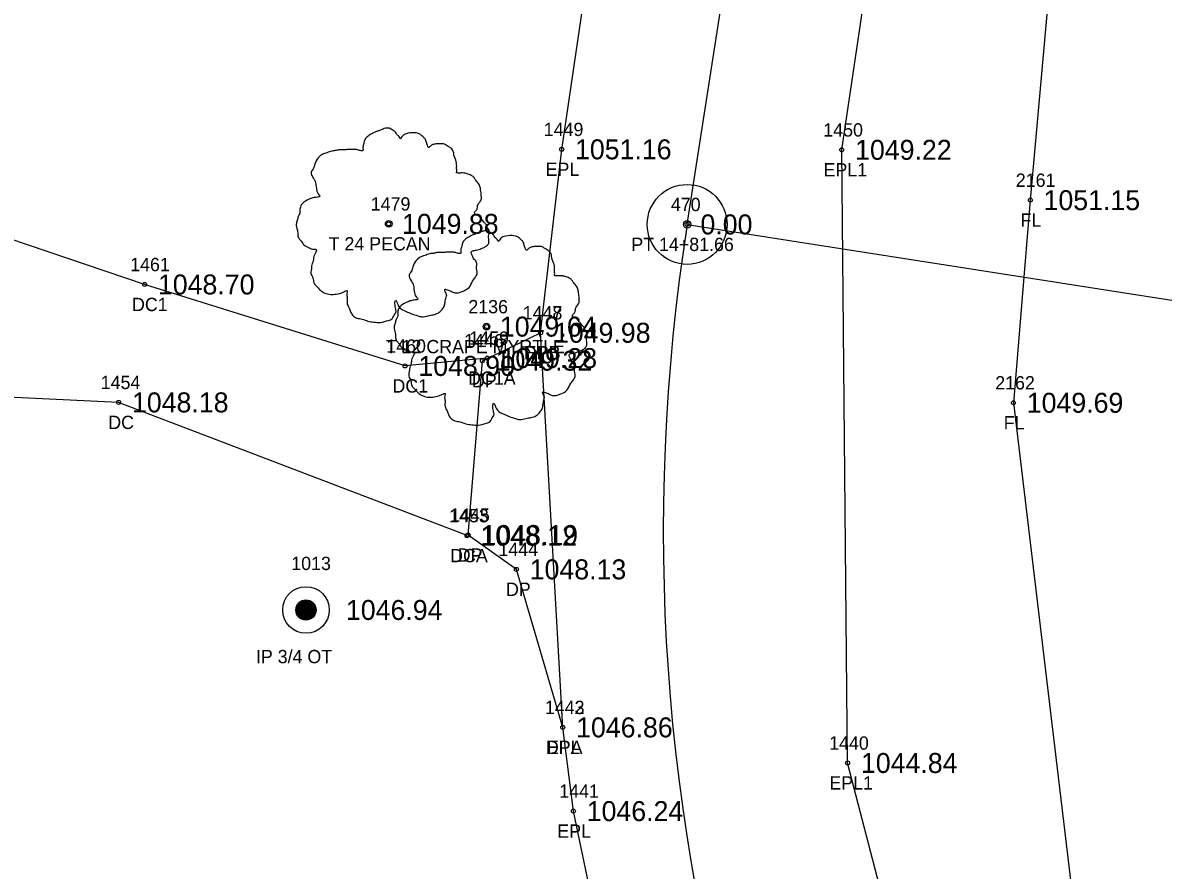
# Model space of a CAD drawing. Extents: x 1578957 to 1581675, y 1115963 to 1120391.
# Drawn here: x 1579731.3 to 1579816.9, y 1117837.9 to 1117901.5 of the extents above; entities that cross this region are included whole.
import ezdxf

# ---------------------------------------------------------------- set-up
doc = ezdxf.new("R2010")
doc.units = 0
for name, color, linetype in [('RD_EX_Conc', 7, 'Continuous'), ('RD_EX_Conc_txCode', 7, 'Continuous'), ('RD_EX_Driveway', 7, 'Continuous'), ('RD_EX_Driveway_txCode', 7, 'Continuous'), ('RD_EX_DV_Prop_txCode', 7, 'Continuous'), ('RD_EX_DV_PropPin', 7, 'Continuous'), ('RD_EX_Fence_Other', 7, 'Continuous'), ('RD_EX_Fence_Other_txCode', 7, 'Continuous'), ('RD_EX_Road', 7, 'Continuous'), ('RD_EX_Road_txCode', 7, 'Continuous'), ('RD_EX_TX_Conc_ELEV', 7, 'Continuous'), ('RD_EX_TX_Driveway_ELEV', 7, 'Continuous'), ('RD_EX_TX_DV_Prop_ELEV', 7, 'Continuous'), ('RD_EX_TX_Fence_Other_ELEV', 7, 'Continuous'), ('RD_EX_TX_Road_ELEV', 7, 'Continuous'), ('RD_EX_TX_VEG_ELEV', 7, 'Continuous'), ('RD_EX_VEG', 7, 'Continuous'), ('RD_EX_VEG_txCode', 7, 'Continuous'), ('RD_HC_Cl', 7, 'Continuous'), ('RD_HC_Data', 7, 'Continuous'), ('RD_HC_Survey_ELEV', 7, 'Continuous'), ('RD_HC_txCode', 7, 'Continuous'), ('RD_SMD_Locator', 7, 'Continuous')]:
    doc.layers.add(name, color=color, linetype=linetype)

msp = doc.modelspace()

# ---------------------------------------------------------------- linework, layer by layer
at = {"layer": 'RD_EX_Conc'}
for points in [[(1579766.13, 1117876.333), (1579759.962, 1117875.743), (1579740.404, 1117881.865), (1579703.901, 1117894.243), (1579686.039, 1117903.999), (1579677.342, 1117923.266), (1579681.088, 1117939.977), (1579691.372, 1117948.591), (1579705.923, 1117954.825), (1579741.024, 1117962.879), (1579773.406, 1117968.489), (1579777.959, 1117966.761), (1579779.093, 1117978.96)], [(1579764.617, 1117862.993), (1579738.454, 1117873.005), (1579671.399, 1117876.222)]]:
    msp.add_lwpolyline(points, dxfattribs=at)
at = {"layer": 'RD_EX_Driveway'}
msp.add_lwpolyline([(1579771.808, 1117848.588), (1579768.323, 1117860.461), (1579764.698, 1117863.037), (1579765.767, 1117876.14), (1579770.145, 1117878.236)], dxfattribs=at)
at = {"layer": 'RD_EX_DV_PropPin'}
for p, q in [((1579752.136, 1117856.752), (1579752.136, 1117858.065)), ((1579752.171, 1117856.733), (1579752.171, 1117858.084)), ((1579752.206, 1117856.716), (1579752.206, 1117858.102)), ((1579752.241, 1117856.701), (1579752.241, 1117858.116)), ((1579752.276, 1117856.688), (1579752.276, 1117858.129)), ((1579752.311, 1117856.677), (1579752.311, 1117858.14)), ((1579752.346, 1117856.668), (1579752.346, 1117858.149)), ((1579752.381, 1117856.661), (1579752.381, 1117858.157)), ((1579752.416, 1117856.655), (1579752.416, 1117858.163)), ((1579752.451, 1117856.651), (1579752.451, 1117858.167)), ((1579752.486, 1117856.649), (1579752.486, 1117858.169)), ((1579752.521, 1117856.648), (1579752.521, 1117858.17)), ((1579752.556, 1117856.649), (1579752.556, 1117858.169)), ((1579752.591, 1117856.651), (1579752.591, 1117858.167)), ((1579752.626, 1117856.655), (1579752.626, 1117858.163)), ((1579752.661, 1117856.661), (1579752.661, 1117858.157)), ((1579752.696, 1117856.668), (1579752.696, 1117858.149)), ((1579752.731, 1117856.677), (1579752.731, 1117858.14)), ((1579752.766, 1117856.688), (1579752.766, 1117858.129)), ((1579752.801, 1117856.701), (1579752.801, 1117858.116)), ((1579752.836, 1117856.716), (1579752.836, 1117858.102)), ((1579752.871, 1117856.733), (1579752.871, 1117858.084)), ((1579752.906, 1117856.752), (1579752.906, 1117858.065)), ((1579751.785, 1117857.213), (1579751.785, 1117857.605)), ((1579751.82, 1117857.111), (1579751.82, 1117857.707)), ((1579751.856, 1117857.039), (1579751.856, 1117857.778)), ((1579751.891, 1117856.982), (1579751.891, 1117857.835)), ((1579751.926, 1117856.935), (1579751.926, 1117857.883)), ((1579751.961, 1117856.894), (1579751.961, 1117857.924)), ((1579751.996, 1117856.858), (1579751.996, 1117857.96)), ((1579752.031, 1117856.827), (1579752.031, 1117857.991)), ((1579752.066, 1117856.799), (1579752.066, 1117858.019)), ((1579752.101, 1117856.774), (1579752.101, 1117858.043)), ((1579752.941, 1117856.774), (1579752.941, 1117858.043)), ((1579752.976, 1117856.799), (1579752.976, 1117858.019)), ((1579753.011, 1117856.827), (1579753.011, 1117857.991)), ((1579753.046, 1117856.858), (1579753.046, 1117857.96)), ((1579753.081, 1117856.894), (1579753.081, 1117857.924)), ((1579753.116, 1117856.935), (1579753.116, 1117857.883)), ((1579753.151, 1117856.982), (1579753.151, 1117857.835)), ((1579753.186, 1117857.039), (1579753.186, 1117857.778)), ((1579753.221, 1117857.111), (1579753.221, 1117857.707)), ((1579753.256, 1117857.213), (1579753.256, 1117857.605))]:
    msp.add_line(p, q, dxfattribs=at)
for radius in [1.75, 0.761]:
    msp.add_circle((1579752.521, 1117857.409), radius, dxfattribs=at)
at = {"layer": 'RD_EX_Fence_Other'}
msp.add_lwpolyline([(1579823.104, 1118041.087), (1579819.64, 1117977.762), (1579811.21, 1117936.274), (1579806.912, 1117888.201), (1579805.65, 1117872.977), (1579810.216, 1117834.804), (1579821.355, 1117805.105), (1579835.234, 1117784.194), (1579851.403, 1117768.05), (1579868.554, 1117757.557), (1579908.33, 1117744.227), (1579949.735, 1117742.637), (1579998.853, 1117745.107), (1580033.637, 1117749.157), (1580057.075, 1117744.228), (1580092.078, 1117730.794), (1580117.524, 1117724.619), (1580141.715, 1117727.925), (1580159.983, 1117735.31), (1580192.445, 1117760.446), (1580226.972, 1117787.769), (1580271.309, 1117822.486), (1580302.096, 1117858.032)], dxfattribs=at)
at = {"layer": 'RD_EX_Road'}
for points in [[(1580132.914, 1117689.949), (1580126.197, 1117690.713), (1580104.514, 1117701.773), (1580054.231, 1117722.915), (1579999.655, 1117728.645), (1579947.034, 1117725.641), (1579902.617, 1117727.901), (1579859.282, 1117741.23), (1579828.335, 1117764.868), (1579804.422, 1117802.726), (1579793.197, 1117845.912), (1579792.758, 1117891.982), (1579799.628, 1117938.215), (1579807.414, 1117987.508), (1579809.684, 1118039.768), (1579804.464, 1118093.359), (1579794.793, 1118143.944)], [(1580121.995, 1117647.598), (1580119.902, 1117658.172), (1580108.554, 1117670.894), (1580093.888, 1117680.496), (1580047.657, 1117700.115), (1579998.943, 1117706.513), (1579949.017, 1117704.446), (1579899.181, 1117706.754), (1579851.312, 1117721.596), (1579810.789, 1117752.923), (1579804.028, 1117759.706), (1579792.304, 1117778.187), (1579787.439, 1117787.947), (1579779.119, 1117811.184), (1579772.603, 1117842.297), (1579771.808, 1117848.588), (1579770.145, 1117878.236), (1579771.725, 1117892.019), (1579778.922, 1117940.842), (1579785.853, 1117982.888), (1579786.73, 1117990.339), (1579789.156, 1118040.245), (1579783.452, 1118089.738), (1579774.288, 1118139.394)]]:
    msp.add_lwpolyline(points, dxfattribs=at)
at = {"layer": 'RD_EX_VEG'}
for centre, radius in [((1579758.734, 1117886.419), 0.25), ((1579758.722, 1117886.401), 0.0001), ((1579766.085, 1117878.698), 0.25), ((1579766.073, 1117878.679), 0.0001)]:
    msp.add_circle(centre, radius, dxfattribs=at)
for points in [[(1579758.866, 1117893.587), (1579758.566, 1117893.612), (1579758.241, 1117893.512), (1579757.992, 1117893.412), (1579757.767, 1117893.337), (1579757.542, 1117893.237), (1579757.242, 1117893.062), (1579757.017, 1117892.862), (1579756.892, 1117892.612), (1579756.842, 1117892.387), (1579756.792, 1117892.112), (1579756.792, 1117891.937), (1579756.667, 1117891.912), (1579756.517, 1117891.937), (1579756.267, 1117892.012), (1579756.017, 1117892.012), (1579755.767, 1117892.012), (1579755.418, 1117891.987), (1579755.068, 1117891.987), (1579754.793, 1117891.937), (1579754.468, 1117891.887), (1579754.093, 1117891.762), (1579753.743, 1117891.637), (1579753.444, 1117891.388), (1579753.194, 1117890.913), (1579753.069, 1117890.563), (1579752.919, 1117890.313), (1579753.069, 1117889.863), (1579753.244, 1117889.513), (1579753.269, 1117889.313), (1579753.344, 1117888.889), (1579753.444, 1117888.664), (1579753.568, 1117888.464), (1579753.494, 1117888.439), (1579753.119, 1117888.389), (1579752.819, 1117888.289), (1579752.394, 1117888.064), (1579752.169, 1117887.839), (1579752.069, 1117887.514), (1579752.044, 1117887.164), (1579751.944, 1117886.965), (1579751.869, 1117886.69), (1579751.844, 1117886.615), (1579751.794, 1117886.29), (1579751.894, 1117885.84), (1579751.919, 1117885.49), (1579752.044, 1117885.265), (1579752.194, 1117885.09), (1579752.369, 1117884.84), (1579752.769, 1117884.616), (1579753.094, 1117884.516), (1579753.294, 1117884.491), (1579753.119, 1117883.991), (1579753.069, 1117883.641), (1579752.944, 1117883.241), (1579752.944, 1117883.166), (1579752.894, 1117882.691), (1579753.044, 1117882.366), (1579753.119, 1117881.992), (1579753.294, 1117881.767), (1579753.568, 1117881.467), (1579753.893, 1117881.242), (1579754.393, 1117881.117), (1579754.793, 1117881.142), (1579755.368, 1117881.317), (1579755.618, 1117881.392), (1579755.593, 1117881.217), (1579755.618, 1117880.842), (1579755.618, 1117880.417), (1579755.767, 1117880.093), (1579755.867, 1117879.818), (1579756.017, 1117879.568), (1579756.342, 1117879.343), (1579756.742, 1117879.268), (1579757.167, 1117879.118), (1579757.617, 1117879.043), (1579758.116, 1117879.018), (1579758.716, 1117879.168), (1579758.991, 1117879.293), (1579759.091, 1117879.468), (1579759.291, 1117879.843), (1579759.241, 1117880.068), (1579759.266, 1117880.667), (1579759.366, 1117880.492), (1579759.541, 1117880.142), (1579760.041, 1117879.843), (1579760.44, 1117879.668), (1579760.915, 1117879.518), (1579761.215, 1117879.443), (1579761.69, 1117879.518), (1579762.065, 1117879.593), (1579762.44, 1117879.718), (1579762.739, 1117879.993), (1579762.914, 1117880.267), (1579762.964, 1117880.542), (1579763.039, 1117880.917), (1579763.089, 1117881.092)], [(1579763.089, 1117881.092), (1579763.014, 1117881.267), (1579762.964, 1117881.517), (1579763.039, 1117881.492), (1579763.214, 1117881.442), (1579763.489, 1117881.317), (1579763.714, 1117881.242), (1579764.039, 1117881.267), (1579764.314, 1117881.367), (1579764.764, 1117881.642), (1579765.038, 1117882.117), (1579765.313, 1117882.516), (1579765.388, 1117882.841), (1579765.338, 1117883.066), (1579765.313, 1117883.566), (1579765.113, 1117883.816), (1579765.063, 1117883.941), (1579764.963, 1117884.341), (1579765.038, 1117884.391), (1579765.313, 1117884.441), (1579765.688, 1117884.566), (1579765.963, 1117884.69), (1579766.188, 1117884.865), (1579766.263, 1117885.09), (1579766.238, 1117885.49), (1579766.288, 1117885.89), (1579766.213, 1117886.04), (1579766.113, 1117886.19), (1579766.038, 1117886.39), (1579765.888, 1117886.54), (1579765.788, 1117886.69), (1579765.688, 1117886.79), (1579765.563, 1117886.94), (1579765.388, 1117887.064), (1579765.238, 1117887.114), (1579765.188, 1117887.264), (1579765.338, 1117887.464), (1579765.388, 1117887.564), (1579765.413, 1117887.789), (1579765.638, 1117888.139), (1579765.688, 1117888.539), (1579765.638, 1117888.964), (1579765.588, 1117889.239), (1579765.438, 1117889.513), (1579765.238, 1117889.763), (1579765.113, 1117889.938), (1579764.938, 1117890.063), (1579764.614, 1117890.188), (1579764.364, 1117890.238), (1579764.014, 1117890.238), (1579763.814, 1117890.288), (1579763.839, 1117890.338), (1579763.839, 1117890.488), (1579763.839, 1117890.763), (1579763.764, 1117891.213), (1579763.614, 1117891.712), (1579763.614, 1117891.737), (1579763.514, 1117891.987), (1579763.289, 1117892.187), (1579763.114, 1117892.287), (1579762.914, 1117892.412), (1579762.664, 1117892.437), (1579762.365, 1117892.437), (1579762.09, 1117892.387), (1579761.89, 1117892.287), (1579761.715, 1117892.162), (1579761.64, 1117892.312), (1579761.54, 1117892.612), (1579761.49, 1117892.762), (1579761.34, 1117892.937), (1579761.115, 1117893.137), (1579760.665, 1117893.262), (1579760.041, 1117893.187), (1579759.741, 1117892.987), (1579759.591, 1117892.812), (1579759.541, 1117892.937), (1579759.341, 1117893.137), (1579759.241, 1117893.312), (1579759.066, 1117893.437), (1579758.916, 1117893.537), (1579758.816, 1117893.587)], [(1579766.217, 1117885.865), (1579765.917, 1117885.89), (1579765.592, 1117885.79), (1579765.342, 1117885.69), (1579765.118, 1117885.615), (1579764.893, 1117885.515), (1579764.593, 1117885.34), (1579764.368, 1117885.14), (1579764.243, 1117884.89), (1579764.193, 1117884.666), (1579764.143, 1117884.391), (1579764.143, 1117884.216), (1579764.018, 1117884.191), (1579763.868, 1117884.216), (1579763.618, 1117884.291), (1579763.368, 1117884.291), (1579763.118, 1117884.291), (1579762.769, 1117884.266), (1579762.419, 1117884.266), (1579762.144, 1117884.216), (1579761.819, 1117884.166), (1579761.444, 1117884.041), (1579761.094, 1117883.916), (1579760.794, 1117883.666), (1579760.545, 1117883.191), (1579760.42, 1117882.841), (1579760.27, 1117882.591), (1579760.42, 1117882.142), (1579760.595, 1117881.792), (1579760.619, 1117881.592), (1579760.694, 1117881.167), (1579760.794, 1117880.942), (1579760.919, 1117880.742), (1579760.844, 1117880.717), (1579760.47, 1117880.667), (1579760.17, 1117880.567), (1579759.745, 1117880.342), (1579759.52, 1117880.118), (1579759.42, 1117879.793), (1579759.395, 1117879.443), (1579759.295, 1117879.243), (1579759.22, 1117878.968), (1579759.195, 1117878.893), (1579759.145, 1117878.568), (1579759.245, 1117878.118), (1579759.27, 1117877.769), (1579759.395, 1117877.544), (1579759.545, 1117877.369), (1579759.72, 1117877.119), (1579760.12, 1117876.894), (1579760.445, 1117876.794), (1579760.644, 1117876.769), (1579760.47, 1117876.269), (1579760.42, 1117875.919), (1579760.295, 1117875.52), (1579760.295, 1117875.445), (1579760.245, 1117874.97), (1579760.395, 1117874.645), (1579760.47, 1117874.27), (1579760.644, 1117874.045), (1579760.919, 1117873.745), (1579761.244, 1117873.52), (1579761.744, 1117873.395), (1579762.144, 1117873.42), (1579762.719, 1117873.595), (1579762.968, 1117873.67), (1579762.943, 1117873.495), (1579762.968, 1117873.121), (1579762.968, 1117872.696), (1579763.118, 1117872.371), (1579763.218, 1117872.096), (1579763.368, 1117871.846), (1579763.693, 1117871.621), (1579764.093, 1117871.546), (1579764.518, 1117871.396), (1579764.968, 1117871.321), (1579765.467, 1117871.296), (1579766.067, 1117871.446), (1579766.342, 1117871.571), (1579766.442, 1117871.746), (1579766.642, 1117872.121), (1579766.592, 1117872.346), (1579766.617, 1117872.946), (1579766.717, 1117872.771), (1579766.892, 1117872.421), (1579767.392, 1117872.121), (1579767.791, 1117871.946), (1579768.266, 1117871.796), (1579768.566, 1117871.721), (1579769.041, 1117871.796), (1579769.416, 1117871.871), (1579769.79, 1117871.996), (1579770.09, 1117872.271), (1579770.265, 1117872.546), (1579770.315, 1117872.821), (1579770.39, 1117873.196), (1579770.44, 1117873.37)], [(1579770.44, 1117873.37), (1579770.365, 1117873.545), (1579770.315, 1117873.795), (1579770.39, 1117873.77), (1579770.565, 1117873.72), (1579770.84, 1117873.595), (1579771.065, 1117873.52), (1579771.39, 1117873.545), (1579771.665, 1117873.645), (1579772.114, 1117873.92), (1579772.389, 1117874.395), (1579772.664, 1117874.795), (1579772.739, 1117875.12), (1579772.689, 1117875.345), (1579772.664, 1117875.844), (1579772.464, 1117876.094), (1579772.414, 1117876.219), (1579772.314, 1117876.619), (1579772.389, 1117876.669), (1579772.664, 1117876.719), (1579773.039, 1117876.844), (1579773.314, 1117876.969), (1579773.539, 1117877.144), (1579773.614, 1117877.369), (1579773.589, 1117877.769), (1579773.639, 1117878.168), (1579773.564, 1117878.318), (1579773.464, 1117878.468), (1579773.389, 1117878.668), (1579773.239, 1117878.818), (1579773.139, 1117878.968), (1579773.039, 1117879.068), (1579772.914, 1117879.218), (1579772.739, 1117879.343), (1579772.589, 1117879.393), (1579772.539, 1117879.543), (1579772.689, 1117879.743), (1579772.739, 1117879.843), (1579772.764, 1117880.068), (1579772.989, 1117880.417), (1579773.039, 1117880.817), (1579772.989, 1117881.242), (1579772.939, 1117881.517), (1579772.789, 1117881.792), (1579772.589, 1117882.042), (1579772.464, 1117882.217), (1579772.289, 1117882.342), (1579771.965, 1117882.467), (1579771.715, 1117882.516), (1579771.365, 1117882.516), (1579771.165, 1117882.566), (1579771.19, 1117882.616), (1579771.19, 1117882.766), (1579771.19, 1117883.041), (1579771.115, 1117883.491), (1579770.965, 1117883.991), (1579770.965, 1117884.016), (1579770.865, 1117884.266), (1579770.64, 1117884.466), (1579770.465, 1117884.566), (1579770.265, 1117884.691), (1579770.015, 1117884.716), (1579769.716, 1117884.716), (1579769.441, 1117884.666), (1579769.241, 1117884.566), (1579769.066, 1117884.441), (1579768.991, 1117884.591), (1579768.891, 1117884.89), (1579768.841, 1117885.04), (1579768.691, 1117885.215), (1579768.466, 1117885.415), (1579768.016, 1117885.54), (1579767.392, 1117885.465), (1579767.092, 1117885.265), (1579766.942, 1117885.09), (1579766.892, 1117885.215), (1579766.692, 1117885.415), (1579766.592, 1117885.59), (1579766.417, 1117885.715), (1579766.267, 1117885.815), (1579766.167, 1117885.865)]]:
    msp.add_spline(points, degree=3, dxfattribs=at)
at = {"layer": 'RD_HC_Cl'}
msp.add_line((1579781.145, 1117886.379), (1579795.16, 1117976.12), dxfattribs=at)
msp.add_arc((1579928.874, 1117863.307), 149.519, 171.12359, 273.23235, dxfattribs=at)
at = {"layer": 'RD_HC_Data'}
msp.add_line((1579781.145, 1117886.379), (1579895.714, 1117868.486), dxfattribs=at)
for radius in [3, 0.282]:
    msp.add_circle((1579781.145, 1117886.379), radius, dxfattribs=at)
at = {"layer": 'RD_SMD_Locator'}
for centre in [(1579771.725, 1117892.019), (1579792.758, 1117891.982), (1579806.912, 1117888.201), (1579758.734, 1117886.419), (1579781.145, 1117886.379), (1579740.404, 1117881.865), (1579766.085, 1117878.698), (1579770.145, 1117878.236), (1579770.145, 1117878.236), (1579765.767, 1117876.14), (1579766.13, 1117876.333), (1579759.962, 1117875.743), (1579738.454, 1117873.005), (1579805.65, 1117872.977), (1579764.617, 1117862.993), (1579764.698, 1117863.037), (1579768.323, 1117860.461), (1579752.521, 1117857.409), (1579771.808, 1117848.588), (1579771.808, 1117848.588), (1579793.197, 1117845.912), (1579772.603, 1117842.297)]:
    msp.add_circle(centre, 0.15, dxfattribs=at)

# ---------------------------------------------------------------- texts
at = {"layer": 'RD_EX_Conc_txCode'}
for s, p in [('1461', (1579739.317, 1117882.865)), ('DC1', (1579739.459, 1117879.865)), ('1460', (1579758.553, 1117876.743)), ('1459', (1579764.784, 1117877.333)), ('DC1A', (1579764.697, 1117874.333)), ('1454', (1579737.108, 1117874.005)), ('DC1', (1579759.017, 1117873.743)), ('DC', (1579737.675, 1117871.005)), ('1453', (1579763.27, 1117863.993)), ('DCA', (1579763.349, 1117860.993))]:
    msp.add_text(s, height=1, dxfattribs=at).set_placement(p)
at = {"layer": 'RD_EX_Driveway_txCode'}
for s, p in [('1447', (1579768.799, 1117879.236)), ('1446', (1579764.397, 1117877.14)), ('DPB', (1579768.893, 1117876.236)), ('DP', (1579764.987, 1117874.14)), ('1445', (1579763.352, 1117864.037)), ('1444', (1579766.976, 1117861.461)), ('DP', (1579763.919, 1117861.037)), ('DP', (1579767.543, 1117858.461)), ('1443', (1579770.461, 1117849.588)), ('DPA', (1579770.54, 1117846.588))]:
    msp.add_text(s, height=1, dxfattribs=at).set_placement(p)
at = {"layer": 'RD_EX_DV_Prop_txCode'}
for s, p in [('1013', (1579751.418, 1117860.409)), ('IP 3/4 OT', (1579748.765, 1117853.409))]:
    msp.add_text(s, height=1, dxfattribs=at).set_placement(p)
at = {"layer": 'RD_EX_Fence_Other_txCode'}
for s, p in [('2161', (1579805.826, 1117889.201)), ('FL', (1579806.18, 1117886.201)), ('2162', (1579804.28, 1117873.977)), ('FL', (1579804.918, 1117870.977))]:
    msp.add_text(s, height=1, dxfattribs=at).set_placement(p)
at = {"layer": 'RD_EX_Road_txCode'}
for s, p in [('1449', (1579770.379, 1117893.019)), ('1450', (1579791.372, 1117892.982)), ('EPL', (1579770.52, 1117890.019)), ('EPL1', (1579791.388, 1117889.982)), ('1448', (1579768.799, 1117879.236)), ('EPL', (1579768.941, 1117876.236)), ('1442', (1579770.461, 1117849.588)), ('1440', (1579791.811, 1117846.912)), ('EPL', (1579770.603, 1117846.588)), ('EPL1', (1579791.827, 1117843.912)), ('1441', (1579771.54, 1117843.297)), ('EPL', (1579771.398, 1117840.297))]:
    msp.add_text(s, height=1, dxfattribs=at).set_placement(p)
at = {"layer": 'RD_EX_TX_Conc_ELEV'}
for s, p in [('1048.70', (1579741.404, 1117881.115)), ('1049.28', (1579767.13, 1117875.583)), ('1048.90', (1579760.962, 1117874.993)), ('1048.18', (1579739.454, 1117872.255)), ('1048.12', (1579765.617, 1117862.243))]:
    msp.add_text(s, height=1.5, dxfattribs=at).set_placement(p)
at = {"layer": 'RD_EX_TX_Driveway_ELEV'}
for s, p in [('1049.98', (1579771.145, 1117877.486)), ('1049.32', (1579766.767, 1117875.39)), ('1048.19', (1579765.698, 1117862.287)), ('1048.13', (1579769.323, 1117859.711)), ('1046.86', (1579772.808, 1117847.838))]:
    msp.add_text(s, height=1.5, dxfattribs=at).set_placement(p)
at = {"layer": 'RD_EX_TX_DV_Prop_ELEV'}
msp.add_text('1046.94', height=1.5, dxfattribs=at).set_placement((1579755.521, 1117856.659))
at = {"layer": 'RD_EX_TX_Fence_Other_ELEV'}
for s, p in [('1051.15', (1579807.912, 1117887.451)), ('1049.69', (1579806.65, 1117872.227))]:
    msp.add_text(s, height=1.5, dxfattribs=at).set_placement(p)
at = {"layer": 'RD_EX_TX_Road_ELEV'}
for s, p in [('1051.16', (1579772.725, 1117891.269)), ('1049.22', (1579793.758, 1117891.232)), ('1049.98', (1579771.145, 1117877.486)), ('1046.86', (1579772.808, 1117847.838)), ('1044.84', (1579794.197, 1117845.162)), ('1046.24', (1579773.603, 1117841.547))]:
    msp.add_text(s, height=1.5, dxfattribs=at).set_placement(p)
at = {"layer": 'RD_EX_TX_VEG_ELEV'}
for s, p in [('1049.88', (1579759.734, 1117885.669)), ('1049.64', (1579767.085, 1117877.948))]:
    msp.add_text(s, height=1.5, dxfattribs=at).set_placement(p)
at = {"layer": 'RD_EX_VEG_txCode'}
for s, p in [('1479', (1579757.388, 1117887.419)), ('T 24 PECAN', (1579754.222, 1117884.419)), ('2136', (1579764.715, 1117879.698)), ('T 12 CRAPE MYRTLE', (1579758.514, 1117876.698))]:
    msp.add_text(s, height=1, dxfattribs=at).set_placement(p)
at = {"layer": 'RD_HC_Survey_ELEV'}
msp.add_text('0.00', height=1.5, dxfattribs=at).set_placement((1579782.145, 1117885.629))
at = {"layer": 'RD_HC_txCode'}
for s, p in [('470', (1579779.925, 1117887.379)), ('PT 14+81.66', (1579776.956, 1117884.379))]:
    msp.add_text(s, height=1, dxfattribs=at).set_placement(p)

doc.saveas('drawing.dxf')
